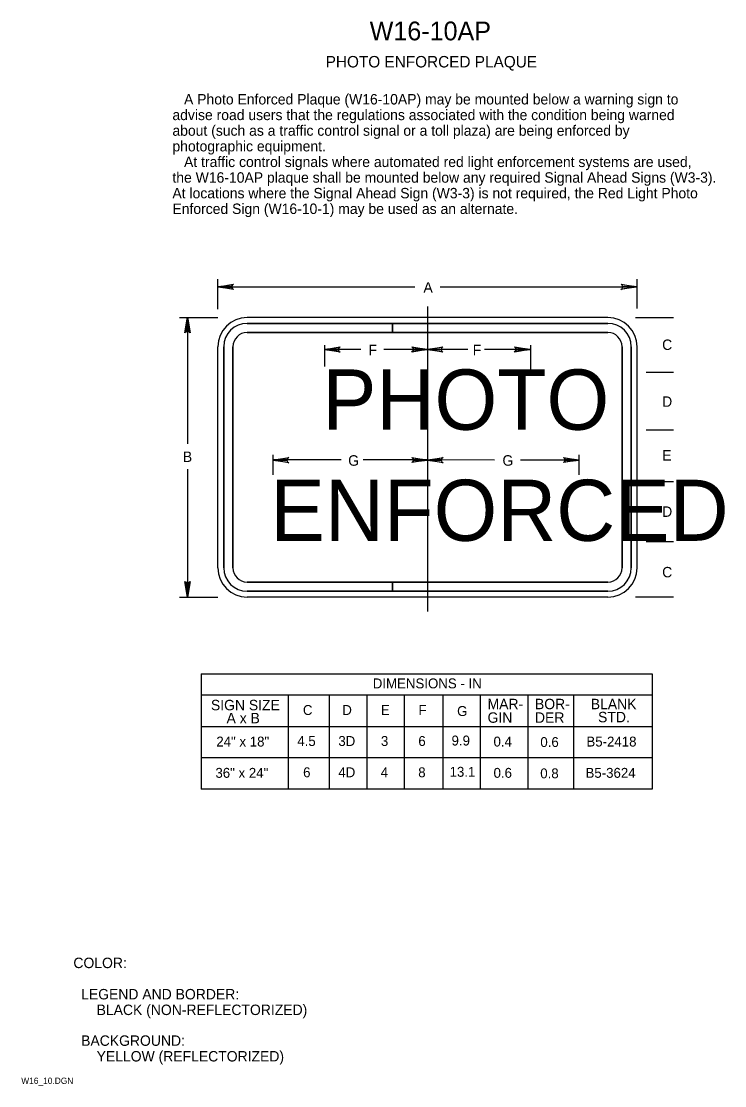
# Model space of a CAD drawing. Extents: x 0.013 to 0.181, y 0.004 to 0.259.
import ezdxf

# ---------------------------------------------------------------- set-up
doc = ezdxf.new("R2010")
doc.units = 0
for name, color, linetype in [('1', 7, 'Continuous'), ('2', 7, 'Continuous'), ('3', 7, 'Continuous')]:
    doc.layers.add(name, color=color, linetype=linetype)

# ---------------------------------------------------------------- blocks, each defined once
blk = doc.blocks.new('RARROW')
at = {"layer": '3'}
for p, q in [((-2.156, 0.285), (-2.2665, 0.384625)), ((-2.2665, 0.384625), (0, 0)), ((0, 0), (-2.2665, -0.379125)), ((-2.156, 0.285), (-2.075625, 0.12075)), ((0, 0), (-2.156, 0.285)), ((-2.14975, -0.2705), (0, 0)), ((-2.075625, 0.12075), (0, 0)), ((0, 0), (-2.074, -0.108)), ((-2.2665, -0.379125), (-2.14975, -0.2705)), ((-2.074, -0.108), (-2.14975, -0.2705))]:
    blk.add_line(p, q, dxfattribs=at)

msp = doc.modelspace()

# ---------------------------------------------------------------- linework, layer by layer
at = {"layer": '1'}
for p, q in [((0.11004, 0.19067), (0.11004, 0.11758)), ((0.05054, 0.18807), (0.05978, 0.18807)), ((0.05255, 0.15782), (0.05255, 0.18807)), ((0.15331, 0.18807), (0.0668, 0.18807)), ((0.0668, 0.18667), (0.09106, 0.18667)), ((0.09106, 0.18667), (0.15331, 0.18667)), ((0.09106, 0.18447), (0.0668, 0.18447)), ((0.15331, 0.18447), (0.09106, 0.18447)), ((0.08532, 0.18144), (0.08532, 0.17636)), ((0.13472, 0.18144), (0.13472, 0.17503)), ((0.0598, 0.12807), (0.0598, 0.18107)), ((0.0612, 0.12807), (0.0612, 0.18107)), ((0.0634, 0.18107), (0.0634, 0.12807)), ((0.15671, 0.12807), (0.15671, 0.18107)), ((0.15891, 0.18107), (0.15891, 0.12807)), ((0.16031, 0.12807), (0.16031, 0.18107)), ((0.16901, 0.17486), (0.16251, 0.17486)), ((0.16031, 0.12807), (0.16031, 0.16407)), ((0.16901, 0.16106), (0.16251, 0.16106)), ((0.07302, 0.15033), (0.07302, 0.15518)), ((0.14642, 0.15033), (0.14642, 0.15518)), ((0.05255, 0.12107), (0.05255, 0.15168)), ((0.16901, 0.14866), (0.16251, 0.14866)), ((0.16901, 0.13428), (0.16251, 0.13428)), ((0.0668, 0.12467), (0.15331, 0.12467)), ((0.15331, 0.12247), (0.0668, 0.12247)), ((0.05054, 0.12107), (0.05978, 0.12107)), ((0.15331, 0.12107), (0.0668, 0.12107)), ((0.16901, 0.12107), (0.15996, 0.12107))]:
    msp.add_line(p, q, dxfattribs=at)
for points in [[(0.0668, 0.18447), (0.09106, 0.18447), (0.10165, 0.18447), (0.10165, 0.18667), (0.09106, 0.18667), (0.0668, 0.18667)], [(0.15331, 0.18667), (0.10165, 0.18667), (0.10165, 0.18447), (0.15331, 0.18447)], [(0.0612, 0.18107), (0.0612, 0.12807)], [(0.0634, 0.12807), (0.0634, 0.15391), (0.0634, 0.18107)], [(0.15671, 0.18107), (0.15671, 0.12807)], [(0.15891, 0.12807), (0.15891, 0.18107)], [(0.10165, 0.12467), (0.0668, 0.12467)], [(0.0668, 0.12247), (0.10165, 0.12247), (0.10165, 0.12467)], [(0.15331, 0.12467), (0.10165, 0.12467), (0.10165, 0.12247), (0.15331, 0.12247)]]:
    msp.add_lwpolyline(points, dxfattribs=at)
for centre, radius, start, end in [((0.0668, 0.18107), 0.007, 90, 180), ((0.0668, 0.18107), 0.0056, 90, 180), ((0.0668, 0.18107), 0.0056, 90, 180), ((0.15331, 0.18107), 0.007, 0, 90), ((0.15331, 0.18107), 0.0056, 0, 90), ((0.15331, 0.18107), 0.0056, 0, 90), ((0.0668, 0.18107), 0.0034, 90, 180), ((0.0668, 0.18107), 0.0034, 90, 180), ((0.15331, 0.18107), 0.0034, 0, 90), ((0.15331, 0.18107), 0.0034, 360, 90), ((0.0668, 0.12807), 0.007, 180, 270), ((0.0668, 0.12807), 0.0056, 180, 270), ((0.0668, 0.12807), 0.0056, 180, 270), ((0.0668, 0.12807), 0.0034, 180, 270), ((0.0668, 0.12807), 0.0034, 180, 270), ((0.15331, 0.12807), 0.007, 270, 0), ((0.15331, 0.12807), 0.0056, 270, 0), ((0.15331, 0.12807), 0.0034, 270, 0), ((0.15331, 0.12807), 0.0034, 270, 0), ((0.15331, 0.12807), 0.0056, 270, 360)]:
    msp.add_arc(centre, radius, start, end, dxfattribs=at)
at = {"layer": '3'}
for p, q in [((0.0598, 0.1901), (0.05979, 0.19723)), ((0.1603, 0.1902), (0.16029, 0.19723)), ((0.10703, 0.19536), (0.05979, 0.19536)), ((0.16029, 0.19536), (0.11306, 0.19536)), ((0.1603, 0.1902), (0.16029, 0.19622)), ((0.15996, 0.18807), (0.169, 0.18808)), ((0.09403, 0.1804), (0.08532, 0.1804)), ((0.11002, 0.1804), (0.09955, 0.1804)), ((0.1197, 0.1804), (0.11002, 0.1804)), ((0.13472, 0.1804), (0.12372, 0.1804)), ((0.08933, 0.15394), (0.07318, 0.15396)), ((0.11003, 0.15392), (0.09464, 0.15394)), ((0.1261, 0.15391), (0.11003, 0.15392)), ((0.14642, 0.15388), (0.13234, 0.1539)), ((0.05581, 0.10268), (0.16396, 0.10268)), ((0.05581, 0.10268), (0.05581, 0.07505)), ((0.16396, 0.10268), (0.16396, 0.07505)), ((0.16396, 0.09755), (0.05581, 0.09755)), ((0.07665, 0.09755), (0.07665, 0.07505)), ((0.1341, 0.09755), (0.1341, 0.07505)), ((0.14503, 0.09755), (0.14503, 0.07505)), ((0.05581, 0.09005), (0.16395, 0.09005)), ((0.16396, 0.08255), (0.05581, 0.08255)), ((0.16396, 0.07505), (0.05581, 0.07505))]:
    msp.add_line(p, q, dxfattribs=at)
for points in [[(0.08646, 0.09755), (0.08646, 0.07505)], [(0.09551, 0.09755), (0.09551, 0.07505)], [(0.10444, 0.09755), (0.10444, 0.07505)], [(0.11369, 0.09755), (0.11369, 0.07505)], [(0.12271, 0.09755), (0.12271, 0.07505)]]:
    msp.add_lwpolyline(points, dxfattribs=at)

# ---------------------------------------------------------------- block references
for p, xscale, yscale, rotation in [((0.05976, 0.19541), 0.0016545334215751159, 0.0016366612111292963, 179.91708286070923), ((0.1602, 0.19541), 0.0016545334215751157, 0.001636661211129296, -0.08291713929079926), ((0.05251, 0.18816), 0.0016545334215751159, 0.0016366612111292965, 90.08291713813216), ((0.08532, 0.1804), 0.0016545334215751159, 0.0016366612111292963, 179.91708286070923), ((0.11001, 0.18041), 0.0016545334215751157, 0.001636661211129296, -0.08291713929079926), ((0.11001, 0.18041), 0.0016545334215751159, 0.0016366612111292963, 179.91708286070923), ((0.13464, 0.18041), 0.0016545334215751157, 0.001636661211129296, -0.08291713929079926), ((0.07302, 0.15391), 0.001654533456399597, 0.0016530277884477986, 179.91625369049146), ((0.11002, 0.15391), 0.0016545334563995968, 0.0016530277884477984, -0.08374630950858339), ((0.11002, 0.15391), 0.001654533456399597, 0.0016530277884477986, 179.91625369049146), ((0.14639, 0.15391), 0.0016545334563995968, 0.0016530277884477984, -0.08374630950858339), ((0.05251, 0.12104), 0.0016545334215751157, 0.0016366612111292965, -89.91708286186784)]:
    msp.add_blockref('RARROW', p, dxfattribs=dict(at, xscale=xscale, yscale=yscale, rotation=rotation))

# ---------------------------------------------------------------- texts
at = {"layer": '1'}
for s, height, p in [('W16-10AP', 0.0045, (0.09618, 0.2545)), ('PHOTO ENFORCED PLAQUE', 0.0027503, (0.08563, 0.248)), ('PHOTO', 0.014459, (0.08488, 0.16116)), ('ENFORCED', 0.014645, (0.07237, 0.13454)), ('COLOR:', 0.0025, (0.02513, 0.03213)), ('  LEGEND AND BORDER:', 0.0024998, (0.02513, 0.02463)), ('      BLACK (NON-REFLECTORIZED)', 0.0024998, (0.02513, 0.02088)), ('  BACKGROUND:', 0.0024998, (0.02513, 0.0135)), ('      YELLOW (REFLECTORIZED)', 0.0024998, (0.02513, 0.00975)), ('W16_10.DGN', 0.0015, (0.01263, 0.00438))]:
    msp.add_text(s, height=height, dxfattribs=at).set_placement(p)
at = {"layer": '2'}
for s, p in [('   A Photo Enforced Plaque (W16-10AP) may be mounted below a warning sign to', (0.04888, 0.23913)), ('advise road users that the regulations associated with the condition being warned', (0.04888, 0.23538)), ('about (such as a traffic control signal or a toll plaza) are being enforced by ', (0.04888, 0.23163)), ('photographic equipment.', (0.04888, 0.22788)), ('   At traffic control signals where automated red light enforcement systems are used,', (0.04888, 0.22413)), ('the W16-10AP plaque shall be mounted below any required Signal Ahead Signs (W3-3).', (0.04888, 0.22038)), ('At locations where the Signal Ahead Sign (W3-3) is not required, the Red Light Photo', (0.04888, 0.21663)), ('Enforced Sign (W16-10-1) may be used as an alternate.', (0.04888, 0.21288))]:
    msp.add_text(s, height=0.0024998, dxfattribs=at).set_placement(p)
at = {"layer": '3'}
for s, height, rotation, p in [('A', 0.0025, 359.9171, (0.10908, 0.19404)), ('F', 0.0025, 359.9171, (0.09589, 0.17904)), ('F', 0.0025, 0.0829, (0.12089, 0.17904)), ('C', 0.0025, 0.0829, (0.16632, 0.18029)), ('D', 0.0025, 0.0829, (0.16632, 0.16666)), ('B', 0.0025, 0.0829, (0.05139, 0.15344)), ('E', 0.0025, 359.9171, (0.16632, 0.15379)), ('G', 0.00252, 359.9163, (0.09102, 0.15254)), ('G', 0.00252, 0.0837, (0.12802, 0.15254)), ('D', 0.0025, 359.9171, (0.16632, 0.14029)), ('C', 0.0025, 359.9171, (0.16632, 0.12579))]:
    msp.add_text(s, height=height, rotation=rotation, dxfattribs=at).set_placement(p)
for s, height, p in [('DIMENSIONS - IN', 0.0023752, (0.09693, 0.09918)), ('SIGN SIZE', 0.0025, (0.05811, 0.09393)), ('C', 0.00238, (0.08017, 0.0928)), ('D', 0.00238, (0.08961, 0.0928)), ('E', 0.00238, (0.09886, 0.0928)), ('F', 0.00238, (0.10789, 0.0928)), ('G', 0.00238, (0.11715, 0.09255)), ('MAR-', 0.0025, (0.12445, 0.09418)), ('BOR-', 0.0025, (0.13582, 0.09418)), ('BLANK', 0.0025, (0.1492, 0.09418)), ('A x B', 0.0025, (0.06186, 0.0908)), ('GIN', 0.0025, (0.12445, 0.09093)), ('DER', 0.0025, (0.13582, 0.09093)), ('STD.', 0.0025, (0.15095, 0.09105)), ('24" x 18"', 0.002375, (0.05941, 0.08524)), ('4.5', 0.002375, (0.07882, 0.08537)), ('3D', 0.002375, (0.08867, 0.08537)), ('3', 0.00238, (0.09888, 0.08537)), ('6', 0.00238, (0.10785, 0.08537)), ('9.9', 0.002375, (0.11582, 0.08549)), ('0.4', 0.002375, (0.12588, 0.08524)), ('0.6', 0.002375, (0.13711, 0.08512)), ('B5-2418', 0.002375, (0.14816, 0.08524)), ('36" x 24"', 0.002375, (0.05919, 0.07774)), ('6', 0.00238, (0.08022, 0.07787)), ('4D', 0.002375, (0.08867, 0.07787)), ('4', 0.00238, (0.09883, 0.07787)), ('8', 0.00238, (0.10783, 0.07787)), ('13.1', 0.002375, (0.11534, 0.07799)), ('0.6', 0.002375, (0.12589, 0.07774)), ('0.8', 0.002375, (0.13709, 0.07762)), ('B5-3624', 0.002375, (0.14794, 0.07774))]:
    msp.add_text(s, height=height, dxfattribs=at).set_placement(p)

doc.saveas('drawing.dxf')
